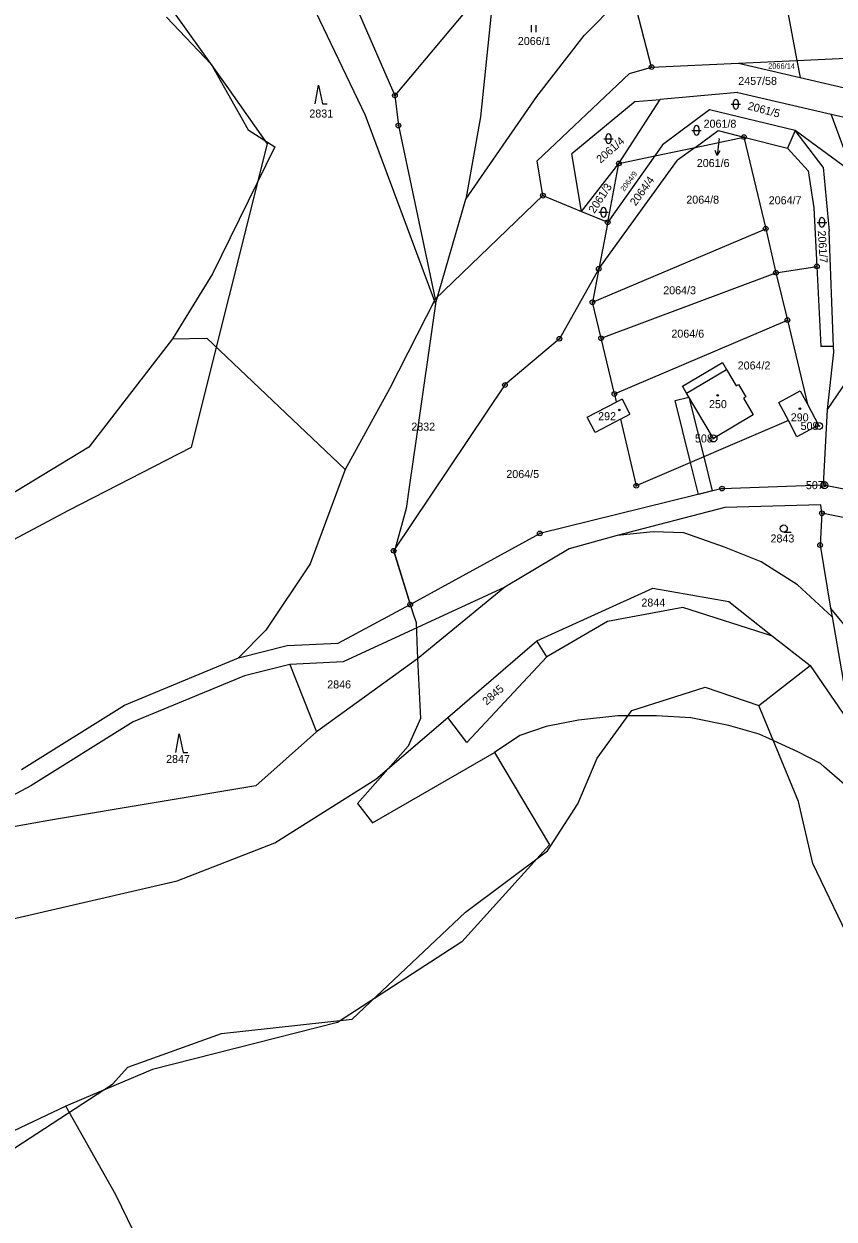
# Model space of a CAD drawing. Extents: x -546762 to -540209, y -1046851 to -1035694.
# Drawn here: x -542696.6 to -542524.6, y -1038439.2 to -1038185.3 of the extents above; entities that cross this region are included whole.
import ezdxf

# ---------------------------------------------------------------- set-up
doc = ezdxf.new("R2010")
doc.units = 0
for name, color, linetype in [('Vrstva 1', 7, 'Continuous'), ('Vrstva 16', 7, 'Continuous'), ('Vrstva 17', 7, 'Continuous'), ('Vrstva 18', 7, 'Continuous'), ('Vrstva 19', 7, 'Continuous'), ('Vrstva 24', 7, 'Continuous'), ('Vrstva 25', 7, 'Continuous'), ('Vrstva 3', 7, 'Continuous'), ('Vrstva 30', 7, 'Continuous'), ('Vrstva 37', 7, 'Continuous'), ('Vrstva 4', 7, 'Continuous'), ('Vrstva 52', 7, 'Continuous'), ('Vrstva 6', 7, 'Continuous')]:
    doc.layers.add(name, color=color, linetype=linetype)

msp = doc.modelspace()

# ---------------------------------------------------------------- linework, layer by layer
at = {"layer": 'Vrstva 1'}
for p, q in [((-542586.42, -1038221.82), (-542587.64, -1038214.43)), ((-542578.23, -1038225.2), (-542580.29, -1038212.94)), ((-542578.23, -1038225.2), (-542570.29, -1038214.97)), ((-542574.55, -1038237.33), (-542557.86, -1038214.29)), ((-542562.64, -1038213.36), (-542572.67, -1038227.47)), ((-542572.67, -1038227.47), (-542570.29, -1038214.97)), ((-542574.55, -1038237.33), (-542575.91, -1038244.45)), ((-542526.86, -1038283.21), (-542525.99, -1038267.23)), ((-542517.56, -1038318.78), (-542525.34, -1038309.43))]:
    msp.add_line(p, q, dxfattribs=at)
for points in [[(-542563.33, -1038194.53), (-542572.26, -1038159.97)], [(-542634.3, -1038162.8), (-542617.85, -1038200.54)], [(-542587.91, -1038164.81), (-542617.85, -1038200.54)], [(-542666.37, -1038183.92), (-542656.85, -1038193.89)], [(-542532.51, -1038193.09), (-542508.54, -1038191.96)], [(-542656.85, -1038193.89), (-542648.98, -1038207.84)], [(-542568.04, -1038195.86), (-542563.33, -1038194.53)], [(-542563.33, -1038194.53), (-542544.89, -1038193.67)], [(-542544.89, -1038193.67), (-542532.51, -1038193.09)], [(-542544.89, -1038193.67), (-542531.83, -1038196.7)], [(-542587.64, -1038214.43), (-542568.04, -1038195.86)], [(-542531.83, -1038196.7), (-542520.23, -1038199.41)], [(-542545, -1038199.9), (-542561.55, -1038201.37)], [(-542545, -1038199.9), (-542525.23, -1038204.51)], [(-542617.85, -1038200.54), (-542617.12, -1038206.95)], [(-542566.83, -1038201.84), (-542580.29, -1038212.94)], [(-542566.83, -1038201.84), (-542561.55, -1038201.37)], [(-542520.58, -1038216.96), (-542525.23, -1038204.51)], [(-542617.12, -1038206.95), (-542609.33, -1038243.77)], [(-542648.98, -1038207.84), (-542643.35, -1038211.48)], [(-542554.12, -1038211.57), (-542543.73, -1038209.39)], [(-542543.73, -1038209.39), (-542539.12, -1038228.83)], [(-542543.73, -1038209.39), (-542534.47, -1038211.71)], [(-542643.35, -1038211.48), (-542656.59, -1038238.42)], [(-542562.64, -1038213.36), (-542554.12, -1038211.57)], [(-542534.47, -1038211.71), (-542530.12, -1038216.58)], [(-542570.29, -1038214.97), (-542562.64, -1038213.36)], [(-542530.12, -1038216.58), (-542528.86, -1038224.4)], [(-542609.33, -1038243.77), (-542586.42, -1038221.82)], [(-542586.42, -1038221.82), (-542578.23, -1038225.2)], [(-542578.23, -1038225.2), (-542572.67, -1038227.47)], [(-542528.86, -1038224.4), (-542528.24, -1038236.83)], [(-542572.67, -1038227.47), (-542574.55, -1038237.33)], [(-542575.91, -1038244.45), (-542539.12, -1038228.83)], [(-542539.12, -1038228.83), (-542536.94, -1038238.2)], [(-542574.55, -1038237.33), (-542582.92, -1038252.2)], [(-542536.94, -1038238.2), (-542528.24, -1038236.83)], [(-542528.24, -1038236.83), (-542527.39, -1038253.83)], [(-542656.59, -1038238.42), (-542665.07, -1038252.24)], [(-542574.08, -1038252.09), (-542536.94, -1038238.2)], [(-542536.94, -1038238.2), (-542534.5, -1038248.26)], [(-542609.33, -1038243.77), (-542619.03, -1038262.83)], [(-542574.08, -1038252.09), (-542575.91, -1038244.45)], [(-542571.25, -1038263.94), (-542534.5, -1038248.26)], [(-542534.5, -1038248.26), (-542530.27, -1038266.1)], [(-542665.07, -1038252.24), (-542682.83, -1038275.23)], [(-542665.07, -1038252.24), (-542657.76, -1038252.06)], [(-542657.76, -1038252.06), (-542628.38, -1038279.97)], [(-542582.92, -1038252.2), (-542594.49, -1038262.03)], [(-542571.25, -1038263.94), (-542574.08, -1038252.09)], [(-542524.71, -1038253.85), (-542527.39, -1038253.83)], [(-542525.99, -1038267.23), (-542516.84, -1038253.85)], [(-542525.99, -1038267.23), (-542524.67, -1038255.05)], [(-542524.67, -1038255.05), (-542524.71, -1038253.85)], [(-542556.77, -1038262.28), (-542548.32, -1038257.28)], [(-542548.32, -1038257.28), (-542547.46, -1038258.73)], [(-542547.46, -1038258.73), (-542545.41, -1038262.2)], [(-542619.03, -1038262.83), (-542628.38, -1038279.97)], [(-542594.49, -1038262.03), (-542618.12, -1038297.22)], [(-542555.91, -1038263.73), (-542556.77, -1038262.28)], [(-542545.41, -1038262.2), (-542544.89, -1038261.89)], [(-542544.89, -1038261.89), (-542543.33, -1038264.54)], [(-542536.35, -1038265.72), (-542531.77, -1038263.28)], [(-542531.77, -1038263.28), (-542530.27, -1038266.1)], [(-542577.02, -1038268.89), (-542570.84, -1038265.65)], [(-542571.25, -1038263.94), (-542570.84, -1038265.65)], [(-542569.62, -1038265.01), (-542570.84, -1038265.65)], [(-542569.62, -1038265.01), (-542567.94, -1038268.21)], [(-542550.21, -1038273.38), (-542555.91, -1038263.73)], [(-542543.33, -1038264.54), (-542543.85, -1038264.85)], [(-542543.85, -1038264.85), (-542541.76, -1038268.38)], [(-542534.29, -1038269.59), (-542536.35, -1038265.72)], [(-542569.97, -1038269.28), (-542567.94, -1038268.21)], [(-542541.76, -1038268.38), (-542550.21, -1038273.38)], [(-542530.27, -1038266.1), (-542527.89, -1038270.57)], [(-542575.34, -1038272.1), (-542577.02, -1038268.89)], [(-542569.97, -1038269.28), (-542575.34, -1038272.1)], [(-542569.97, -1038269.28), (-542566.59, -1038283.43)], [(-542534.29, -1038269.59), (-542566.59, -1038283.43)], [(-542532.47, -1038273.01), (-542534.29, -1038269.59)], [(-542527.89, -1038270.57), (-542532.47, -1038273.01)], [(-542682.83, -1038275.23), (-542704.38, -1038288.26)], [(-542628.38, -1038279.97), (-542635.85, -1038299.98)], [(-542548.38, -1038284.02), (-542526.86, -1038283.21)], [(-542526.86, -1038283.21), (-542520.66, -1038284.45)], [(-542548.38, -1038284.02), (-542587.09, -1038293.56)], [(-542547.82, -1038288.02), (-542570.64, -1038294.02)], [(-542527.44, -1038287.5), (-542547.82, -1038288.02)], [(-542527.19, -1038289.28), (-542527.44, -1038287.5)], [(-542527.19, -1038289.28), (-542527.55, -1038296.02)], [(-542520.94, -1038290.53), (-542527.19, -1038289.28)], [(-542614.61, -1038308.66), (-542587.09, -1038293.56)], [(-542563.04, -1038293.18), (-542570.64, -1038294.02)], [(-542556.53, -1038293.43), (-542563.04, -1038293.18)], [(-542547.87, -1038296.46), (-542556.53, -1038293.43)], [(-542570.64, -1038294.02), (-542580.83, -1038296.8)], [(-542527.55, -1038296.02), (-542525.34, -1038309.43)], [(-542618.12, -1038297.22), (-542614.61, -1038308.66)], [(-542580.83, -1038296.8), (-542594.48, -1038304.98)], [(-542540.06, -1038299.6), (-542547.87, -1038296.46)], [(-542635.85, -1038299.98), (-542645.29, -1038314.08)], [(-542532.37, -1038304.47), (-542540.06, -1038299.6)], [(-542594.48, -1038304.98), (-542628.81, -1038320.82)], [(-542594.48, -1038304.98), (-542613.03, -1038320.15)], [(-542587.71, -1038316.34), (-542563.07, -1038305.21)], [(-542563.07, -1038305.21), (-542546.96, -1038308.02)], [(-542525.02, -1038311.29), (-542532.37, -1038304.47)], [(-542629.91, -1038316.85), (-542614.61, -1038308.66)], [(-542546.96, -1038308.02), (-542537.64, -1038315.34)], [(-542556.74, -1038309.27), (-542572.68, -1038312.27)], [(-542537.64, -1038315.34), (-542556.74, -1038309.27)], [(-542525.34, -1038309.43), (-542525.02, -1038311.29)], [(-542525.02, -1038311.29), (-542521.02, -1038334.17)], [(-542645.29, -1038314.08), (-542651.07, -1038319.95)], [(-542572.68, -1038312.27), (-542585.59, -1038319.77)], [(-542606.62, -1038332.62), (-542587.71, -1038316.34)], [(-542585.59, -1038319.77), (-542587.71, -1038316.34)], [(-542537.64, -1038315.34), (-542529.7, -1038321.57)], [(-542651.07, -1038319.95), (-542640.72, -1038317.36)], [(-542640.72, -1038317.36), (-542629.91, -1038316.85)], [(-542675.25, -1038330), (-542651.07, -1038319.95)], [(-542640.13, -1038321.36), (-542649.8, -1038323.78)], [(-542628.81, -1038320.82), (-542640.13, -1038321.36)], [(-542640.13, -1038321.36), (-542634.52, -1038335.72)], [(-542613.03, -1038320.15), (-542634.52, -1038335.72)], [(-542585.59, -1038319.77), (-542602.61, -1038337.98)], [(-542540.6, -1038330.07), (-542529.7, -1038321.57)], [(-542529.7, -1038321.57), (-542521.02, -1038334.17)], [(-542649.8, -1038323.78), (-542673.4, -1038333.59)], [(-542567.55, -1038331.16), (-542551.99, -1038326.19)], [(-542551.99, -1038326.19), (-542540.6, -1038330.07)], [(-542697.18, -1038343.66), (-542675.25, -1038330)], [(-542574.88, -1038341.3), (-542567.55, -1038331.16)], [(-542532.16, -1038350.5), (-542540.6, -1038330.07)], [(-542673.4, -1038333.59), (-542695.17, -1038347.15)], [(-542621.87, -1038345.75), (-542606.62, -1038332.62)], [(-542602.61, -1038337.98), (-542606.62, -1038332.62)], [(-542634.52, -1038335.72), (-542647.4, -1038347.17)], [(-542578.98, -1038351.01), (-542574.88, -1038341.3)], [(-542695.17, -1038347.15), (-542705.6, -1038352.68)], [(-542643.36, -1038359.25), (-542621.87, -1038345.75)], [(-542647.4, -1038347.17), (-542690.54, -1038354.4)], [(-542585.46, -1038360.93), (-542578.98, -1038351.01)], [(-542529.13, -1038363.66), (-542532.16, -1038350.5)], [(-542690.54, -1038354.4), (-542727.09, -1038360.87)], [(-542664.11, -1038367.3), (-542643.36, -1038359.25)], [(-542602.85, -1038373.97), (-542585.46, -1038360.93)], [(-542508.87, -1038405.78), (-542529.13, -1038363.66)], [(-542707.87, -1038377.44), (-542664.11, -1038367.3)], [(-542626.91, -1038396.74), (-542602.85, -1038373.97)], [(-542654.65, -1038399.73), (-542626.91, -1038396.74)], [(-542674.55, -1038406.87), (-542654.65, -1038399.73)], [(-542677.83, -1038410.5), (-542674.55, -1038406.87)], [(-542700.21, -1038425.08), (-542677.83, -1038410.5)]]:
    msp.add_lwpolyline(points, dxfattribs=at)
at = {"layer": 'Vrstva 16'}
msp.add_line((-542549.08, -1038210.28), (-542549.44, -1038213.26), dxfattribs=at)
for points in [[(-542549.02, -1038209.78), (-542549.08, -1038210.28)], [(-542548.82, -1038212.33), (-542549.44, -1038213.26), (-542549.82, -1038212.21)]]:
    msp.add_lwpolyline(points, dxfattribs=at)
at = {"layer": 'Vrstva 24'}
for centre, radius in [((-542563.33, -1038194.53), 0.5), ((-542563.33, -1038194.53), 0.1), ((-542617.85, -1038200.54), 0.5), ((-542617.85, -1038200.54), 0.1), ((-542617.12, -1038206.95), 0.5), ((-542617.12, -1038206.95), 0.1), ((-542543.73, -1038209.39), 0.5), ((-542543.73, -1038209.39), 0.1), ((-542570.29, -1038214.97), 0.5), ((-542570.29, -1038214.97), 0.1), ((-542586.42, -1038221.82), 0.5), ((-542586.42, -1038221.82), 0.1), ((-542572.67, -1038227.47), 0.5), ((-542572.67, -1038227.47), 0.1), ((-542539.12, -1038228.83), 0.5), ((-542539.12, -1038228.83), 0.1), ((-542574.55, -1038237.33), 0.5), ((-542574.55, -1038237.33), 0.1), ((-542536.94, -1038238.2), 0.5), ((-542528.24, -1038236.83), 0.5), ((-542528.24, -1038236.83), 0.1), ((-542536.94, -1038238.2), 0.1), ((-542575.91, -1038244.45), 0.5), ((-542575.91, -1038244.45), 0.1), ((-542534.5, -1038248.26), 0.5), ((-542534.5, -1038248.26), 0.1), ((-542582.92, -1038252.2), 0.5), ((-542582.92, -1038252.2), 0.1), ((-542574.08, -1038252.09), 0.5), ((-542574.08, -1038252.09), 0.1), ((-542594.49, -1038262.03), 0.5), ((-542594.49, -1038262.03), 0.1), ((-542571.25, -1038263.94), 0.5), ((-542571.25, -1038263.94), 0.1), ((-542527.78, -1038270.73), 0.75), ((-542527.78, -1038270.73), 0.1), ((-542550.21, -1038273.38), 0.75), ((-542550.21, -1038273.38), 0.1), ((-542566.59, -1038283.43), 0.5), ((-542566.59, -1038283.43), 0.1), ((-542548.38, -1038284.02), 0.5), ((-542526.65, -1038283.3), 0.75), ((-542526.86, -1038283.21), 0.5), ((-542526.86, -1038283.21), 0.1), ((-542526.65, -1038283.3), 0.1), ((-542548.38, -1038284.02), 0.1), ((-542527.19, -1038289.28), 0.5), ((-542527.19, -1038289.28), 0.1), ((-542587.09, -1038293.56), 0.5), ((-542587.09, -1038293.56), 0.1), ((-542527.55, -1038296.02), 0.5), ((-542527.55, -1038296.02), 0.1), ((-542618.12, -1038297.22), 0.5), ((-542618.12, -1038297.22), 0.1), ((-542614.61, -1038308.66), 0.5), ((-542614.61, -1038308.66), 0.1)]:
    msp.add_circle(centre, radius, dxfattribs=at)
at = {"layer": 'Vrstva 25'}
for p, q in [((-542588.83, -1038187.13), (-542588.83, -1038185.63)), ((-542587.83, -1038187.13), (-542587.83, -1038185.63)), ((-542546.43, -1038202.42), (-542544.43, -1038202.42)), ((-542545.93, -1038202.92), (-542545.93, -1038201.92)), ((-542544.93, -1038201.92), (-542544.93, -1038202.92)), ((-542554.3, -1038208.45), (-542554.3, -1038207.45)), ((-542553.3, -1038207.45), (-542553.3, -1038208.45)), ((-542573.48, -1038209.72), (-542571.48, -1038209.72)), ((-542572.98, -1038210.22), (-542572.98, -1038209.22)), ((-542571.98, -1038209.22), (-542571.98, -1038210.22)), ((-542554.8, -1038207.95), (-542552.8, -1038207.95)), ((-542574.04, -1038225.86), (-542574.04, -1038224.86)), ((-542573.04, -1038224.86), (-542573.04, -1038225.86)), ((-542574.54, -1038225.36), (-542572.54, -1038225.36)), ((-542528.16, -1038227.49), (-542526.16, -1038227.49)), ((-542527.66, -1038227.99), (-542527.66, -1038226.99)), ((-542526.66, -1038226.99), (-542526.66, -1038227.99)), ((-542535.28, -1038293.26), (-542533.68, -1038293.26))]:
    msp.add_line(p, q, dxfattribs=at)
for points in [[(-542634.75, -1038202.33), (-542634.05, -1038198.33), (-542633.25, -1038202.33), (-542632.25, -1038202.33)], [(-542664.34, -1038340.09), (-542663.64, -1038336.09), (-542662.84, -1038340.09), (-542661.84, -1038340.09)]]:
    msp.add_lwpolyline(points, dxfattribs=at)
for centre, radius in [((-542549.3, -1038264.24), 0.175), ((-542570.21, -1038267.33), 0.175), ((-542531.86, -1038267.04), 0.175), ((-542535.28, -1038292.51), 0.75)]:
    msp.add_circle(centre, radius, dxfattribs=at)
for centre, start, end in [((-542545.43, -1038201.92), 0, 180), ((-542545.43, -1038202.92), 180, 0), ((-542553.8, -1038207.45), 0, 180), ((-542572.48, -1038209.22), 0, 180), ((-542553.8, -1038208.45), 180, 0), ((-542572.48, -1038210.22), 180, 0), ((-542573.54, -1038224.86), 0, 180), ((-542573.54, -1038225.86), 180, 0), ((-542527.16, -1038226.99), 0, 180), ((-542527.16, -1038227.99), 180, 0)]:
    msp.add_arc(centre, 0.5, start, end, dxfattribs=at)
at = {"layer": 'Vrstva 3'}
for points in [[(-542555.91, -1038263.73), (-542547.46, -1038258.73)], [(-542547.46, -1038258.73), (-542545.41, -1038262.2)], [(-542545.41, -1038262.2), (-542544.89, -1038261.89)], [(-542544.89, -1038261.89), (-542543.33, -1038264.54)], [(-542536.35, -1038265.72), (-542531.77, -1038263.28)], [(-542531.77, -1038263.28), (-542530.27, -1038266.1)], [(-542577.02, -1038268.89), (-542570.84, -1038265.65)], [(-542569.62, -1038265.01), (-542570.84, -1038265.65)], [(-542569.62, -1038265.01), (-542567.94, -1038268.21)], [(-542550.21, -1038273.38), (-542555.91, -1038263.73)], [(-542543.33, -1038264.54), (-542543.85, -1038264.85)], [(-542543.85, -1038264.85), (-542541.76, -1038268.38)], [(-542534.29, -1038269.59), (-542536.35, -1038265.72)], [(-542569.97, -1038269.28), (-542567.94, -1038268.21)], [(-542541.76, -1038268.38), (-542550.21, -1038273.38)], [(-542530.27, -1038266.1), (-542527.89, -1038270.57)], [(-542575.34, -1038272.1), (-542577.02, -1038268.89)], [(-542569.97, -1038269.28), (-542575.34, -1038272.1)], [(-542532.47, -1038273.01), (-542534.29, -1038269.59)], [(-542527.89, -1038270.57), (-542532.47, -1038273.01)]]:
    msp.add_lwpolyline(points, dxfattribs=at)
at = {"layer": 'Vrstva 30'}
for p, q in [((-542558.37, -1038265.32), (-542555.41, -1038264.58)), ((-542555.09, -1038278.5), (-542558.37, -1038265.32)), ((-542555.41, -1038264.58), (-542552.28, -1038277.3)), ((-542553.41, -1038285.26), (-542555.09, -1038278.5)), ((-542552.28, -1038277.3), (-542550.49, -1038284.54)), ((-542550.49, -1038284.54), (-542553.41, -1038285.26))]:
    msp.add_line(p, q, dxfattribs=at)
at = {"layer": 'Vrstva 37'}
for centre in [(-542549.3, -1038264.24), (-542570.21, -1038267.33), (-542531.86, -1038267.04)]:
    msp.add_circle(centre, 0.175, dxfattribs=at)
at = {"layer": 'Vrstva 4'}
msp.add_lwpolyline([(-542555.91, -1038263.73), (-542547.46, -1038258.73)], dxfattribs=at)
at = {"layer": 'Vrstva 52'}
for points in [[(-542605.36, -1038101.99), (-542601.33, -1038109.17), (-542598.49, -1038116.94), (-542597.97, -1038119.59), (-542597.2, -1038123.48), (-542596.4, -1038127.55), (-542595.65, -1038139.5), (-542596.82, -1038169.39), (-542597.04, -1038175.13), (-542597.3, -1038181.77), (-542599.65, -1038205.05), (-542602.79, -1038222.57)], [(-542814.84, -1038260.47), (-542791.36, -1038246.2), (-542739.18, -1038316.25), (-542709.61, -1038300.57), (-542687.09, -1038288.63), (-542661.06, -1038275.2), (-542644.88, -1038210.79), (-542653.5, -1038198.63), (-542667.1, -1038179.44), (-542648.82, -1038167.31), (-542628.21, -1038149.33), (-542634.67, -1038182.85), (-542629.06, -1038194.52), (-542624.17, -1038204.71), (-542609.2, -1038244.78)], [(-542602.79, -1038222.57), (-542587.68, -1038200.79), (-542577.68, -1038187.78), (-542570.36, -1038180.46)], [(-542609.2, -1038244.78), (-542602.79, -1038222.57)], [(-542609.2, -1038244.78), (-542613.32, -1038273.46), (-542614.73, -1038283.25), (-542615.45, -1038288.26), (-542618.04, -1038297.53), (-542614.02, -1038310.38), (-542613.37, -1038312.46)], [(-542613.37, -1038312.46), (-542613.11, -1038318.42), (-542613.03, -1038320.14), (-542612.44, -1038332.87), (-542615.04, -1038338.76), (-542625.77, -1038350.9), (-542622.63, -1038355.02), (-542596.67, -1038340.08)], [(-542519.74, -1038349.17), (-542526.62, -1038343.21), (-542527.51, -1038342.44), (-542532.29, -1038339.9), (-542538.34, -1038337.15), (-542540.5, -1038336.17), (-542546.93, -1038334.37), (-542554.99, -1038332.73), (-542562.31, -1038332.28), (-542565.42, -1038332.28), (-542570.53, -1038332.28), (-542578.89, -1038333.18), (-542585.76, -1038334.52), (-542591.29, -1038336.47), (-542596.67, -1038340.08)], [(-542596.67, -1038340.08), (-542585.03, -1038359.67), (-542603.63, -1038380.25), (-542630.03, -1038397.44), (-542669.31, -1038407.43), (-542683.88, -1038413.55), (-542687.72, -1038415.16)], [(-542687.72, -1038415.16), (-542698.94, -1038420.48), (-542725.54, -1038435.79), (-542740.92, -1038453.31), (-542741.35, -1038454.19), (-542747.57, -1038466.86), (-542771.63, -1038475.16), (-542776.28, -1038504.44), (-542756.08, -1038526.38), (-542754.14, -1038528.49), (-542759.81, -1038529.6)], [(-542669.21, -1038517.65), (-542667.85, -1038514.81), (-542666.99, -1038512.7), (-542665.97, -1038510.2), (-542665.73, -1038509.35), (-542664.69, -1038505.59), (-542663.49, -1038499.19), (-542662.98, -1038493.04), (-542662.98, -1038485.44), (-542663.39, -1038477.02), (-542664.28, -1038468.95), (-542665.48, -1038462.98), (-542667.72, -1038455.5), (-542670.26, -1038448.48), (-542673.39, -1038441.75), (-542677.13, -1038433.98), (-542687.72, -1038415.16)]]:
    msp.add_lwpolyline(points, dxfattribs=at)
at = {"layer": 'Vrstva 6'}
for points in [[(-542540.06, -1038152.71), (-542532.51, -1038193.09)], [(-542532.51, -1038193.09), (-542531.83, -1038196.7)], [(-542570.29, -1038214.97), (-542561.55, -1038201.37)], [(-542551.03, -1038203.6), (-542561, -1038211.05)], [(-542532.87, -1038208), (-542551.03, -1038203.6)], [(-542525.23, -1038204.51), (-542520.86, -1038205.53)], [(-542554.12, -1038211.57), (-542549.22, -1038208.01)], [(-542549.22, -1038208.01), (-542543.73, -1038209.39)], [(-542532.87, -1038208), (-542534.47, -1038211.71)], [(-542520.58, -1038216.96), (-542532.87, -1038208)], [(-542526.89, -1038215.79), (-542532.87, -1038208)], [(-542561, -1038211.05), (-542562.64, -1038213.36)], [(-542554.12, -1038211.57), (-542557.86, -1038214.29)], [(-542526.89, -1038215.79), (-542525.61, -1038229.36)], [(-542524.71, -1038253.85), (-542525.61, -1038229.36)]]:
    msp.add_lwpolyline(points, dxfattribs=at)

# ---------------------------------------------------------------- texts
at = {"layer": 'Vrstva 16'}
msp.add_text('2061/6', height=1.7, dxfattribs=at).set_placement((-542553.75, -1038215.74))
at = {"layer": 'Vrstva 17'}
for s, p in [('509', (-542531.7, -1038271.58)), ('508', (-542554.13, -1038274.23)), ('507', (-542530.58, -1038284.15))]:
    msp.add_text(s, height=1.7, dxfattribs=at).set_placement(p)
at = {"layer": 'Vrstva 18'}
for s, height, p in [('2066/1', 1.7, (-542591.75, -1038189.83)), ('2066/14', 1.14, (-542538.6, -1038194.86)), ('2457/58', 1.7, (-542544.94, -1038198.3)), ('2831', 1.7, (-542636.02, -1038205.23)), ('2061/8', 1.7, (-542552.3, -1038207.39)), ('2061/6', 0.1, (-542549.24, -1038209.78)), ('2064/8', 1.7, (-542555.97, -1038223.52)), ('2064/7', 1.7, (-542538.47, -1038223.65)), ('2064/3', 1.7, (-542560.87, -1038242.76)), ('2064/6', 1.7, (-542559.14, -1038251.98)), ('2064/2', 1.7, (-542545.06, -1038258.73)), ('2832', 1.7, (-542614.37, -1038271.73)), ('2064/5', 1.7, (-542594.19, -1038281.78)), ('2843', 1.7, (-542538.09, -1038295.47)), ('2844', 1.7, (-542565.51, -1038309.08)), ('2846', 1.7, (-542632.22, -1038326.47)), ('2847', 1.7, (-542666.44, -1038342.3))]:
    msp.add_text(s, height=height, dxfattribs=at).set_placement(p)
for s, height, rotation, p in [('2061/5', 1.7, 344.9954, (-542543.06, -1038203.48)), ('2061/4', 1.7, 41.1411, (-542574.17, -1038215.04)), ('2064/9', 1.14, 53.4049, (-542569.17, -1038221.03)), ('2061/3', 1.7, 56.7, (-542575.48, -1038225.72)), ('2064/4', 1.7, 54.1274, (-542566.73, -1038224.13)), ('2061/7', 1.7, 273.5344, (-542528.06, -1038229.28)), ('2845', 1.7, 41.0132, (-542598.37, -1038330.12))]:
    msp.add_text(s, height=height, rotation=rotation, dxfattribs=at).set_placement(p)
at = {"layer": 'Vrstva 19'}
for s, p in [('250', (-542551.15, -1038266.94)), ('292', (-542574.69, -1038269.5)), ('290', (-542533.79, -1038269.75))]:
    msp.add_text(s, height=1.7, dxfattribs=at).set_placement(p)

doc.saveas('drawing.dxf')
